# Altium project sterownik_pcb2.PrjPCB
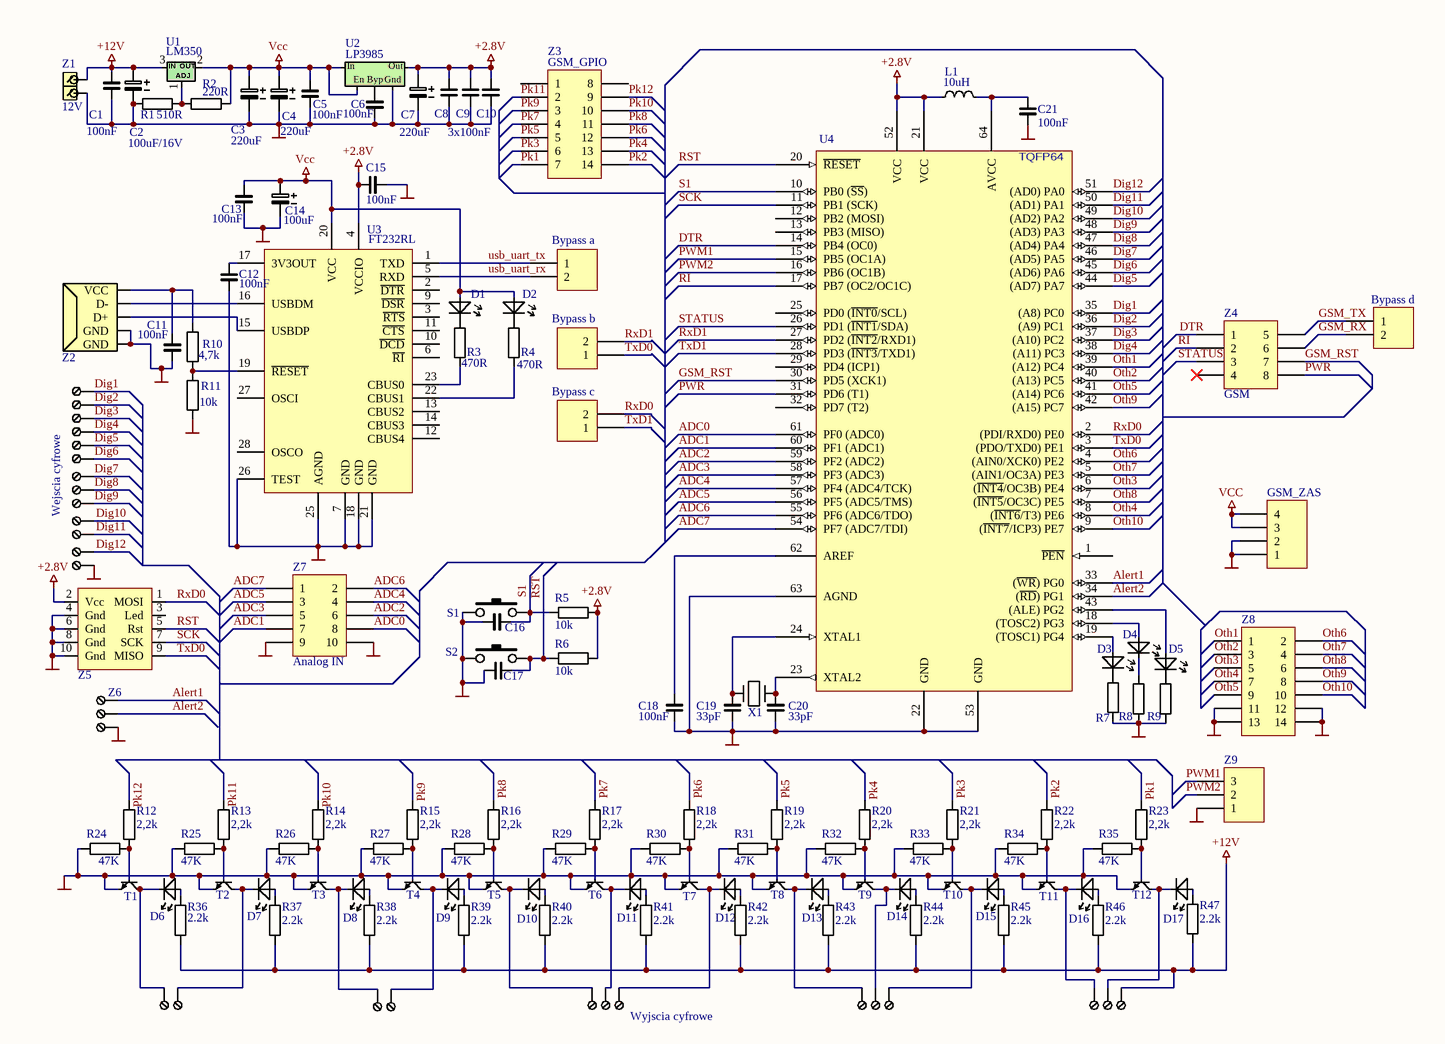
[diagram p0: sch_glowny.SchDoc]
1 sheet, 129 parts. Net scope: global (net labels, ports and power ports of the same name join across sheets).
Board file: glowna.PcbDoc

## Sheet sch_glowny.SchDoc
size A3

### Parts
A2  ARK2_1  [ARK2]  (value not drawn)
A3  ARK3  [ARK3]  (value not drawn)
A4  ARK3  [ARK3]  (value not drawn)
A5  ARK3  [ARK3]  (value not drawn)
A6  ARK3  [ARK3]  (value not drawn)
A7  ARK3  [ARK3]  (value not drawn)
A8  ARK2_1  [ARK2]  (value not drawn)
A9  ARK2_1  [ARK2]  (value not drawn)
Bypass_a  Header 2  [HDR1X2]  (value not drawn)
Bypass_b  Header 2  [HDR1X2]  (value not drawn)
Bypass_c  Header 2  [HDR1X2]  (value not drawn)
Bypass_d  Header 2  [HDR1X2]  (value not drawn)
C1  100nF  [0603]
C2  100uF/16V  [smd-d]
C3  220uF  [smd-d]
C4  220uF  [smd-d]
C5  100nF  [0603]
C6  100nF  [0603]
C7  220uF  [smd-d]
C8  3x100nF  [0603]  (value not drawn)
C9  3x100nF  [0603]  (value not drawn)
C10  3x100nF  [0603]
C11  100nF  [0603]
C12  100nF  [0603]
C13  100nF  [0603]
C14  100uF  [C el./2.5mm]
C15  100nF  [0603]
C16  33pF  [0603]  (value not drawn)
C17  33pF  [0603]  (value not drawn)
C18  100nF  [0603]
C19  33pF  [0603]
C20  33pF  [0603]
C21  100nF  [0603]
D1  (no value)  [led_0805]
D2  (no value)  [led_0805]
D3  (no value)  [led_0805]
D4  (no value)  [led_0805]
D5  (no value)  [led_0805]
D6  (no value)  [led_0805]
D7  (no value)  [led_0805]
D8  (no value)  [led_0805]
D9  (no value)  [led_0805]
D10  (no value)  [led_0805]
D11  (no value)  [led_0805]
D12  (no value)  [led_0805]
D13  (no value)  [led_0805]
D14  (no value)  [led_0805]
D15  (no value)  [led_0805]
D16  (no value)  [led_0805]
D17  (no value)  [led_0805]
GSM_ZAS  Header 4  [HDR1X4]  (value not drawn)
L1  10uH  [r4]
R1  510R  [1206]
R2  220R  [1206]
R3  470R  [1206]
R4  470R  [1206]
R5  10k  [1206]
R6  10k  [1206]
R7  1k  [1206]  (value not drawn)
R8  1k  [1206]  (value not drawn)
R9  1k  [1206]  (value not drawn)
R10  4,7k  [1206]
R11  10k  [1206]
R12  2,2k  [1206]
R13  2,2k  [1206]
R14  2,2k  [1206]
R15  2,2k  [1206]
R16  2,2k  [1206]
R17  2,2k  [1206]
R18  2,2k  [1206]
R19  2,2k  [1206]
R20  2,2k  [1206]
R21  2,2k  [1206]
R22  2,2k  [1206]
R23  2,2k  [1206]
R24  47K  [1206]
R25  47K  [1206]
R26  47K  [1206]
R27  47K  [1206]
R28  47K  [1206]
R29  47K  [1206]
R30  47K  [1206]
R31  47K  [1206]
R32  47K  [1206]
R33  47K  [1206]
R34  47K  [1206]
R35  47K  [1206]
R36  2.2k  [1206]
R37  2.2k  [1206]
R38  2.2k  [1206]
R39  2.2k  [1206]
R40  2.2k  [1206]
R41  2.2k  [1206]
R42  2.2k  [1206]
R43  2.2k  [1206]
R44  2.2k  [1206]
R45  2.2k  [1206]
R46  2.2k  [1206]
R47  2.2k  [1206]
S1  MSWITCH  [MSWITCH]  (value not drawn)
S2  MSWITCH  [MSWITCH]  (value not drawn)
T1  BC548B  [sot-23 rk]  (value not drawn)
T2  BC548B  [sot-23 rk]  (value not drawn)
T3  BC548B  [sot-23 rk]  (value not drawn)
T4  BC548B  [sot-23 rk]  (value not drawn)
T5  BC548B  [sot-23 rk]  (value not drawn)
T6  BC548B  [sot-23 rk]  (value not drawn)
T7  BC548B  [sot-23 rk]  (value not drawn)
T8  BC548B  [sot-23 rk]  (value not drawn)
T9  BC548B  [sot-23 rk]  (value not drawn)
T10  BC548B  [sot-23 rk]  (value not drawn)
T11  BC548B  [sot-23 rk]  (value not drawn)
T12  BC548B  [sot-23 rk]  (value not drawn)
U1  LM350  [to220v]
U2  LP3985  [sot23-5al]
U3  FT232RL  [SSOP-28]
U4  ATMEGA128_TQFP64  [atmega128]  (value not drawn)
Wejscia_cyfrowe  ARK2_1  [ARK2]  (value not drawn)
Wyjscia_cyfrowe  ARK3  [ARK3]  (value not drawn)
X1  X  [X]  (value not drawn)
Z1  12V  [ARK2]
Z2  USB_con  [usb2.5-2h4f]  (value not drawn)
Z3  GSM_GPIO  [HDR2X7_CEN]
Z4  GSM  [HDR2X4_CEN]
Z5  AVR_PROG  [hdr2x5]  (value not drawn)
Z6  ARK3  [ARK3]  (value not drawn)
Z7  Analog IN  [idc2.54-v10d]
Z8  Header 7X2  [idc2.54-v14c]  (value not drawn)
Z9  Header 3  [ark3]  (value not drawn)

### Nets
+2.8V: C7.1 C8.1 C9.1 C10.1 C15.1 L1.2 R5.2(BOT) R6.2(BOT) U2.5(Out) U3.4(VCCIO) U4.21(VCC) U4.52(VCC) Z5.2(Vcc)
+12V: C1.1 C2.1 R36.1(TOP) R37.1(TOP) R38.1(TOP) R39.1(TOP) R40.1(TOP) R41.1(TOP) R42.1(TOP) R43.1(TOP) R44.1(TOP) R45.1(TOP) R46.1(TOP) R47.1(TOP) U1.3 Wyjscia_cyfrowe.3 Z1.1
GND: C1.2 C2.2 C3.2 C4.2 C5.2 C6.1 C7.2 C8.2 C9.2 C10.2 C11.2 C12.2 C13.2 C14.2 C15.2 C16.1 C17.1 C18.2 C19.2 C20.2 C21.1 GSM_ZAS.1 GSM_ZAS.2 R1.1(TOP) R7.1(TOP) R8.1(TOP) R9.1(TOP) R11.1(TOP) R24.1(TOP) R25.1(TOP) R26.1(TOP) R27.1(TOP) R28.1(TOP) R29.1(TOP) R30.1(TOP) R31.1(TOP) R32.1(TOP) R33.1(TOP) R34.1(TOP) R35.1(TOP) S1.1 S2.1 T1.1(C) T2.1(C) T3.1(C) T4.1(C) T5.1(C) T6.1(C) T7.1(C) T8.1(C) T9.1(C) T10.1(C) T11.1(C) T12.1(C) U2.2(Gnd) U3.7(GND) U3.18(GND) U3.21(GND) U3.25(AGND) U3.26(TEST) U4.22(GND) U4.53(GND) U4.63(AGND) Wejscia_cyfrowe.1 Z1.2 Z2.4(GND) Z2.5(GND) Z5.4(Gnd) Z5.6(Gnd) Z5.8(Gnd) Z5.10(Gnd) Z6.3 Z7.9 Z7.10 Z8.11 Z8.12 Z8.13 Z8.14 Z9.1
NC: U3.8(NC) U3.24(NC)
Vcc: C3.1 C4.1 C5.1 C13.1 C14.1 D1.1(K) D2.1(K) GSM_ZAS.3 GSM_ZAS.4 R2.2(BOT) U1.2(VOUT) U2.1(In) U2.3(En) U3.20(VCC)
ADC0: U4.61(PF0_(ADC0)) Z7.8
ADC1: U4.60(PF1_(ADC1)) Z7.7
ADC2: U4.59(PF2_(ADC2)) Z7.6
ADC3: U4.58(PF3_(ADC3)) Z7.5
ADC4: U4.57(PF4_(ADC4/TCK)) Z7.4
ADC5: U4.56(PF5_(ADC5/TMS)) Z7.3
ADC6: U4.55(PF6_(ADC6/TDO)) Z7.2
ADC7: U4.54(PF7_(ADC7/TDI)) Z7.1
Alert1: U4.33((~{WR})_PG0) Z6.1
Alert2: U4.34((~{RD})_PG1) Z6.2
Dig1: A5.3 U4.35((A8)_PC0)
Dig2: A5.2 U4.36((A9)_PC1)
Dig3: A5.1 U4.37((A10)_PC2)
Dig4: A4.3 U4.38((A11)_PC3)
Dig5: A4.2 U4.44((AD7)_PA7)
Dig6: A4.1 U4.45((AD6)_PA6)
Dig7: A3.3 U4.46((AD5)_PA5)
Dig8: A3.2 U4.47((AD4)_PA4)
Dig9: A3.1 U4.48((AD3)_PA3)
Dig10: A2.2 U4.49((AD2)_PA2)
Dig11: A2.1 U4.50((AD1)_PA1)
Dig12: U4.51((AD0)_PA0) Wejscia_cyfrowe.2
DTR: U4.14(PB4_(OC0)) Z4.1
GSM_RST: U4.30(PD5_(XCK1)) Z4.7
GSM_RX: Bypass_d.2 Z4.6
GSM_TX: Bypass_d.1 Z4.5
Oth1: U4.39((A12)_PC4) Z8.1
Oth2: U4.40((A13)_PC5) Z8.3
Oth3: U4.6((~{INT4}/OC3B)_PE4) Z8.5
Oth4: U4.8((~{INT6}/T3)_PE6) Z8.7
Oth5: U4.41((A14)_PC6) Z8.9
Oth6: U4.4((AIN0/XCK0)_PE2) Z8.2
Oth7: U4.5((AIN1/OC3A)_PE3) Z8.4
Oth8: U4.7((~{INT5}/OC3C)_PE5) Z8.6
Oth9: U4.42((A15)_PC7) Z8.8
Oth10: U4.9((~{INT7}/ICP3)_PE7) Z8.10
Pk1: R23.2(BOT) Z3.7
Pk2: R22.2(BOT) Z3.14
Pk3: R21.2(BOT) Z3.6
Pk4: R20.2(BOT) Z3.13
Pk5: R19.2(BOT) Z3.5
Pk6: R18.2(BOT) Z3.12
Pk7: R17.2(BOT) Z3.4
Pk8: R16.2(BOT) Z3.11
Pk9: R15.2(BOT) Z3.3
Pk10: R14.2(BOT) Z3.10
Pk11: R13.2(BOT) Z3.2
Pk12: R12.2(BOT) Z3.9
PWM1: U4.15(PB5_(OC1A)) Z9.3
PWM2: U4.16(PB6_(OC1B)) Z9.2
PWR: U4.31(PD6_(T1)) Z4.8
RI: U4.17(PB7_(OC2/OC1C)) Z4.2
RST: C17.2 R6.1(TOP) S2.2 U4.20(~{RESET}) Z5.5(Rst)
RxD0: Bypass_c.2 U4.2((PDI/RXD0)_PE0) Z5.1(MOSI)
RxD1: Bypass_b.2 U4.27(PD2_(~{INT2}/RXD1))
S1: C16.2 R5.1(TOP) S1.2 U4.10(PB0_(~{SS}))
SCK: U4.11(PB1_(SCK)) Z5.7(SCK)
STATUS: U4.26(PD1_(~{INT1}/SDA)) Z4.3
TxD0: Bypass_b.1 U4.3((PDO/TXD0)_PE1) Z5.9(MISO)
TxD1: Bypass_c.1 U4.28(PD3_(~{INT3}/TXD1))
usb_uart_rx: Bypass_a.2 U3.5(RXD)
usb_uart_tx: Bypass_a.1 U3.1(TXD)
NetA6_1: A6.1 D13.2(A) T8.3(E)
NetA6_2: A6.2 D14.2(A) T9.3(E)
NetA6_3: A6.3 D15.2(A) T10.3(E)
NetA7_1: A7.1 D10.2(A) T5.3(E)
NetA7_2: A7.2 D11.2(A) T6.3(E)
NetA7_3: A7.3 D12.2(A) T7.3(E)
NetA8_1: A8.1 D8.2(A) T3.3(E)
NetA8_2: A8.2 D9.2(A) T4.3(E)
NetA9_1: A9.1 D6.2(A) T1.3(E)
NetA9_2: A9.2 D7.2(A) T2.3(E)
NetC6_2: C6.2 U2.4(Byp)
NetC11_1: C11.1 R10.2(BOT) Z2.1(VCC)
NetC12_1: C12.1 U3.17(3V3OUT)
NetC18_1: C18.1 U4.62(AREF)
NetC19_1: C19.1 U4.24(XTAL1) X1.1
NetC20_1: C20.1 U4.23(XTAL2) X1.2
NetC21_2: C21.2 L1.1 U4.64(AVCC)
NetD1_2: D1.2(A) R3.2(BOT)
NetD2_2: D2.2(A) R4.2(BOT)
NetD3_1: D3.1(A) U4.19((TOSC1)_PG4)
NetD3_2: D3.2(K) R7.2(BOT)
NetD4_1: D4.1(A) U4.18((TOSC2)_PG3)
NetD4_2: D4.2(K) R8.2(BOT)
NetD5_1: D5.1(A) U4.43((ALE)_PG2)
NetD5_2: D5.2(K) R9.2(BOT)
NetD6_1: D6.1(K) R36.2(BOT)
NetD7_1: D7.1(K) R37.2(BOT)
NetD8_1: D8.1(K) R38.2(BOT)
NetD9_1: D9.1(K) R39.2(BOT)
NetD10_1: D10.1(K) R40.2(BOT)
NetD11_1: D11.1(K) R41.2(BOT)
NetD12_1: D12.1(K) R42.2(BOT)
NetD13_1: D13.1(K) R43.2(BOT)
NetD14_1: D14.1(K) R44.2(BOT)
NetD15_1: D15.1(K) R45.2(BOT)
NetD16_1: D16.1(K) R46.2(BOT)
NetD16_2: D16.2(A) T11.3(E) Wyjscia_cyfrowe.1
NetD17_1: D17.1(K) R47.2(BOT)
NetD17_2: D17.2(A) T12.3(E) Wyjscia_cyfrowe.2
NetR1_2: R1.2(BOT) R2.1(TOP) U1.1(GND)
NetR3_1: R3.1(TOP) U3.23(CBUS0)
NetR4_1: R4.1(TOP) U3.22(CBUS1)
NetR10_1: R10.1(TOP) R11.2(BOT) U3.19(~{RESET})
NetR12_1: R12.1(TOP) R24.2(BOT) T1.2(B)
NetR13_1: R13.1(TOP) R25.2(BOT) T2.2(B)
NetR14_1: R14.1(TOP) R26.2(BOT) T3.2(B)
NetR15_1: R15.1(TOP) R27.2(BOT) T4.2(B)
NetR16_1: R16.1(TOP) R28.2(BOT) T5.2(B)
NetR17_1: R17.1(TOP) R29.2(BOT) T6.2(B)
NetR18_1: R18.1(TOP) R30.2(BOT) T7.2(B)
NetR19_1: R19.1(TOP) R31.2(BOT) T8.2(B)
NetR20_1: R20.1(TOP) R32.2(BOT) T9.2(B)
NetR21_1: R21.1(TOP) R33.2(BOT) T10.2(B)
NetR22_1: R22.1(TOP) R34.2(BOT) T11.2(B)
NetR23_1: R23.1(TOP) R35.2(BOT) T12.2(B)
NetU3_15: U3.15(USBDP) Z2.3(D+)
NetU3_16: U3.16(USBDM) Z2.2(D-)

Not connected (* = marked no-connect by the designer): U3 2(~{DTR}) 3(~{RTS}) 6(~{RI}) 9(~{DSR}) 10(~{DCD}) 11(~{CTS}) 12(CBUS4) 13(CBUS2) 14(CBUS3) 27(OSCI) 28(OSCO); U4 1(~{PEN}) 12(PB2_(MOSI)) 13(PB3_(MISO)) 25(PD0_(~{INT0}/SCL)) 29(PD4_(ICP1)) 32(PD7_(T2)); Z3 1 8; Z4 4*; Z5 3(Led)

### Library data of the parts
Bypass_a Bypass_b Bypass_c Bypass_d = Header 2: Header, 2-Pin
C1 C5 C6 C8-C13 C15-C21 = CAP: Condenstor
C2-C4 C7 C14 = CAP2: kONDENSATOR ELEKTROLITYCZNY
D1-D17 = LED0: dioda elektroluminescencyjna LED
GSM_ZAS = Header 4: Header, 4-Pin
L1 = cewka
R1-R47 = RES: Rezystor
T1-T12 = BC548B: Tranzystor NPN
U1 = LM317: 3-Terminal Adjustable Positive Voltage Regulator
U2 = LM3985: Stabilizator 2.8V
U3 = IC_FT232RL: FT232R USB UART
U4 = ATMEGA128_TQFP64: Atmel AVR 8bit - Mega Family
X1 = X: Kwarc
Z1 = ARK
Z3 = Header 7X2A: Header, 7-Pin, Dual row
Z4 = Header 4X2A: Header, 4-Pin, Dual row
Z7 = Header 5X2: Header, 5-Pin, Dual row
Z8 = Header 7X2: Header, 7-Pin, Dual row
Z9 = Header 3: Header, 3-Pin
